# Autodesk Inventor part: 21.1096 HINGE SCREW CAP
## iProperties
Created: 2007-01
Part Number: 21.1096 HINGE SCREW CAP
Material: PVC-U
Document SubType Name: Modeling
Designer: Andy Moles
Mass: 0.689926 g
Surface Area: 8.66268 cm^2
Volume: 0.492804 cm^3
Density: 1.4 g/cm^3
Author: Andy Moles
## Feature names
1. Extrusion1
